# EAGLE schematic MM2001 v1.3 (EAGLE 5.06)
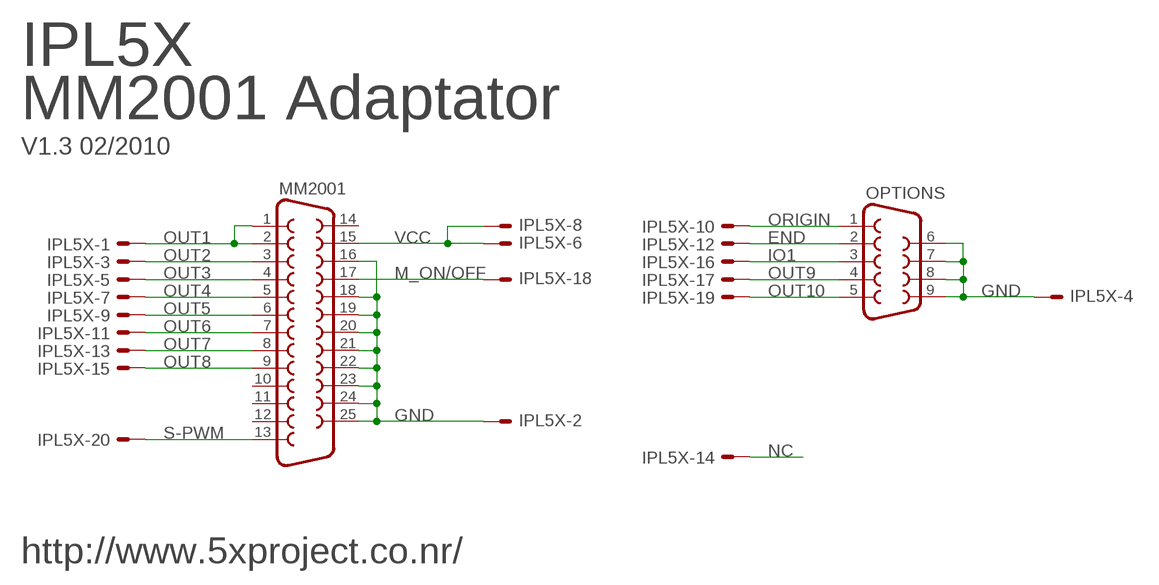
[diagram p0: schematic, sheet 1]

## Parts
IPL5X  ML20E  [ML20]
MM2001  F25HP  [F25HP]
OPTIONS  F09HP  [F09HP]

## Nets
END: IPL5X.12 OPTIONS.2
GND: IPL5X.2 IPL5X.4 MM2001.16 MM2001.18 MM2001.19 MM2001.20 MM2001.21 MM2001.22 MM2001.23 MM2001.24 MM2001.25 OPTIONS.6 OPTIONS.7 OPTIONS.8 OPTIONS.9
IO1: IPL5X.16 OPTIONS.3
M_ON/OFF: IPL5X.18 MM2001.17
NC: IPL5X.14
ORIGIN: IPL5X.10 OPTIONS.1
OUT1: IPL5X.1 MM2001.1 MM2001.2
OUT2: IPL5X.3 MM2001.3
OUT3: IPL5X.5 MM2001.4
OUT4: IPL5X.7 MM2001.5
OUT5: IPL5X.9 MM2001.6
OUT6: IPL5X.11 MM2001.7
OUT7: IPL5X.13 MM2001.8
OUT8: IPL5X.15 MM2001.9
OUT9: IPL5X.17 OPTIONS.4
OUT10: IPL5X.19 OPTIONS.5
S-PWM: IPL5X.20 MM2001.13
VCC: IPL5X.6 IPL5X.8 MM2001.15
Unconnected: MM2001.10 MM2001.11 MM2001.12 MM2001.14

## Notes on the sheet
- IPL5X
- MM2001 Adaptator
- V1.3 02/2010
- http://www.5xproject.co.nr/

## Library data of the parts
IPL5X = con-harting-ml:ML20?E: HARTING
MM2001 = con-subd:F25: SUB-D
OPTIONS = con-subd:F09: SUB-D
